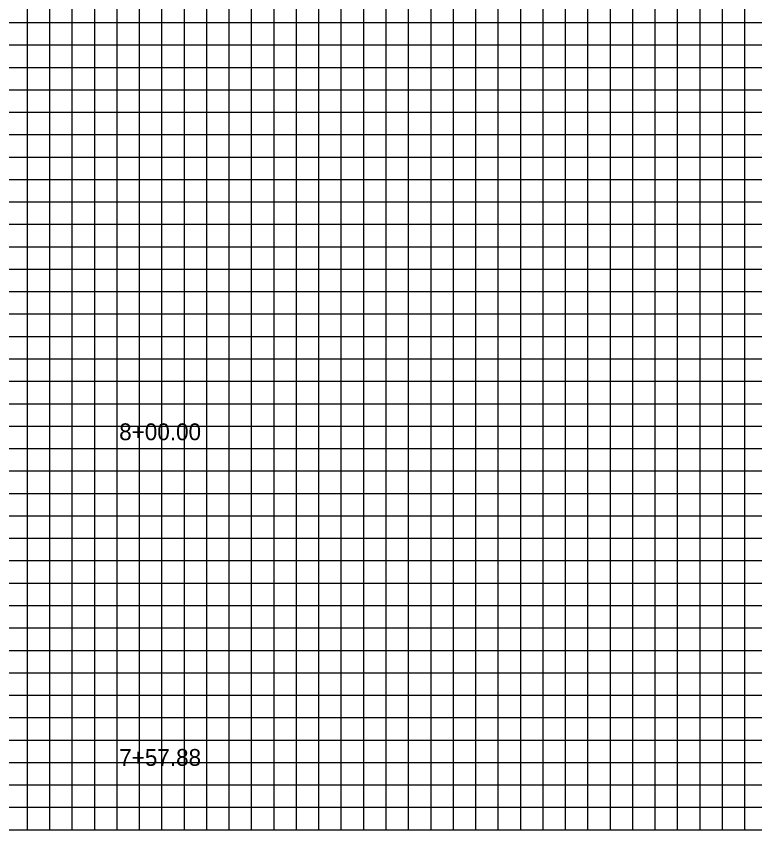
# Model space of a CAD drawing. Extents: x 967 to 1326, y 964 to 3144.
# Drawn here: x 1147 to 1212.9, y 1000 to 1072.6 of the extents above; entities that cross this region are included whole.
import ezdxf

# ---------------------------------------------------------------- set-up
doc = ezdxf.new("R2010")
doc.units = 0
for name, color, linetype in [('Default', 7, 'Continuous'), ('RD_SHT_MjGrid', 7, 'Continuous'), ('RD_SHT_MnGrid', 7, 'Continuous')]:
    doc.layers.add(name, color=color, linetype=linetype)

msp = doc.modelspace()

# ---------------------------------------------------------------- linework, layer by layer
at = {"layer": 'RD_SHT_MjGrid'}
for p, q in [((1150, 1000), (1150, 1170)), ((1160, 1000), (1160, 1170)), ((1170, 1000), (1170, 1170)), ((1180, 1000), (1180, 1170)), ((1190, 1000), (1190, 1170)), ((1200, 1000), (1200, 1170)), ((1210, 1000), (1210, 1170)), ((1000, 1070), (1320, 1070)), ((1000, 1060), (1320, 1060)), ((1000, 1050), (1320, 1050)), ((1000, 1040), (1320, 1040)), ((1000, 1030), (1320, 1030)), ((1000, 1020), (1320, 1020)), ((1000, 1010), (1320, 1010)), ((1000, 1000), (1320, 1000))]:
    msp.add_line(p, q, dxfattribs=at)
at = {"layer": 'RD_SHT_MnGrid'}
for p, q in [((1148, 1000), (1148, 1170)), ((1152, 1000), (1152, 1170)), ((1154, 1000), (1154, 1170)), ((1156, 1000), (1156, 1170)), ((1158, 1000), (1158, 1170)), ((1162, 1000), (1162, 1170)), ((1164, 1000), (1164, 1170)), ((1166, 1000), (1166, 1170)), ((1168, 1000), (1168, 1170)), ((1172, 1000), (1172, 1170)), ((1174, 1000), (1174, 1170)), ((1176, 1000), (1176, 1170)), ((1178, 1000), (1178, 1170)), ((1182, 1000), (1182, 1170)), ((1184, 1000), (1184, 1170)), ((1186, 1000), (1186, 1170)), ((1188, 1000), (1188, 1170)), ((1192, 1000), (1192, 1170)), ((1194, 1000), (1194, 1170)), ((1196, 1000), (1196, 1170)), ((1198, 1000), (1198, 1170)), ((1202, 1000), (1202, 1170)), ((1204, 1000), (1204, 1170)), ((1206, 1000), (1206, 1170)), ((1208, 1000), (1208, 1170)), ((1212, 1000), (1212, 1170)), ((1000, 1072), (1320, 1072)), ((1000, 1068), (1320, 1068)), ((1000, 1066), (1320, 1066)), ((1000, 1064), (1320, 1064)), ((1000, 1062), (1320, 1062)), ((1000, 1058), (1320, 1058)), ((1000, 1056), (1320, 1056)), ((1000, 1054), (1320, 1054)), ((1000, 1052), (1320, 1052)), ((1000, 1048), (1320, 1048)), ((1000, 1046), (1320, 1046)), ((1000, 1044), (1320, 1044)), ((1000, 1042), (1320, 1042)), ((1000, 1038), (1320, 1038)), ((1000, 1036), (1320, 1036)), ((1000, 1034), (1320, 1034)), ((1000, 1032), (1320, 1032)), ((1000, 1028), (1320, 1028)), ((1000, 1026), (1320, 1026)), ((1000, 1024), (1320, 1024)), ((1000, 1022), (1320, 1022)), ((1000, 1018), (1320, 1018)), ((1000, 1016), (1320, 1016)), ((1000, 1014), (1320, 1014)), ((1000, 1012), (1320, 1012)), ((1000, 1008), (1320, 1008)), ((1000, 1006), (1320, 1006)), ((1000, 1004), (1320, 1004)), ((1000, 1002), (1320, 1002))]:
    msp.add_line(p, q, dxfattribs=at)

# ---------------------------------------------------------------- texts
at = {"layer": 'Default'}
for s, p in [('8+00.00', (1156.179, 1034.744)), ('7+57.88', (1156.183, 1005.699))]:
    msp.add_text(s, height=1.5, dxfattribs=at).set_placement(p)

doc.saveas('drawing.dxf')
